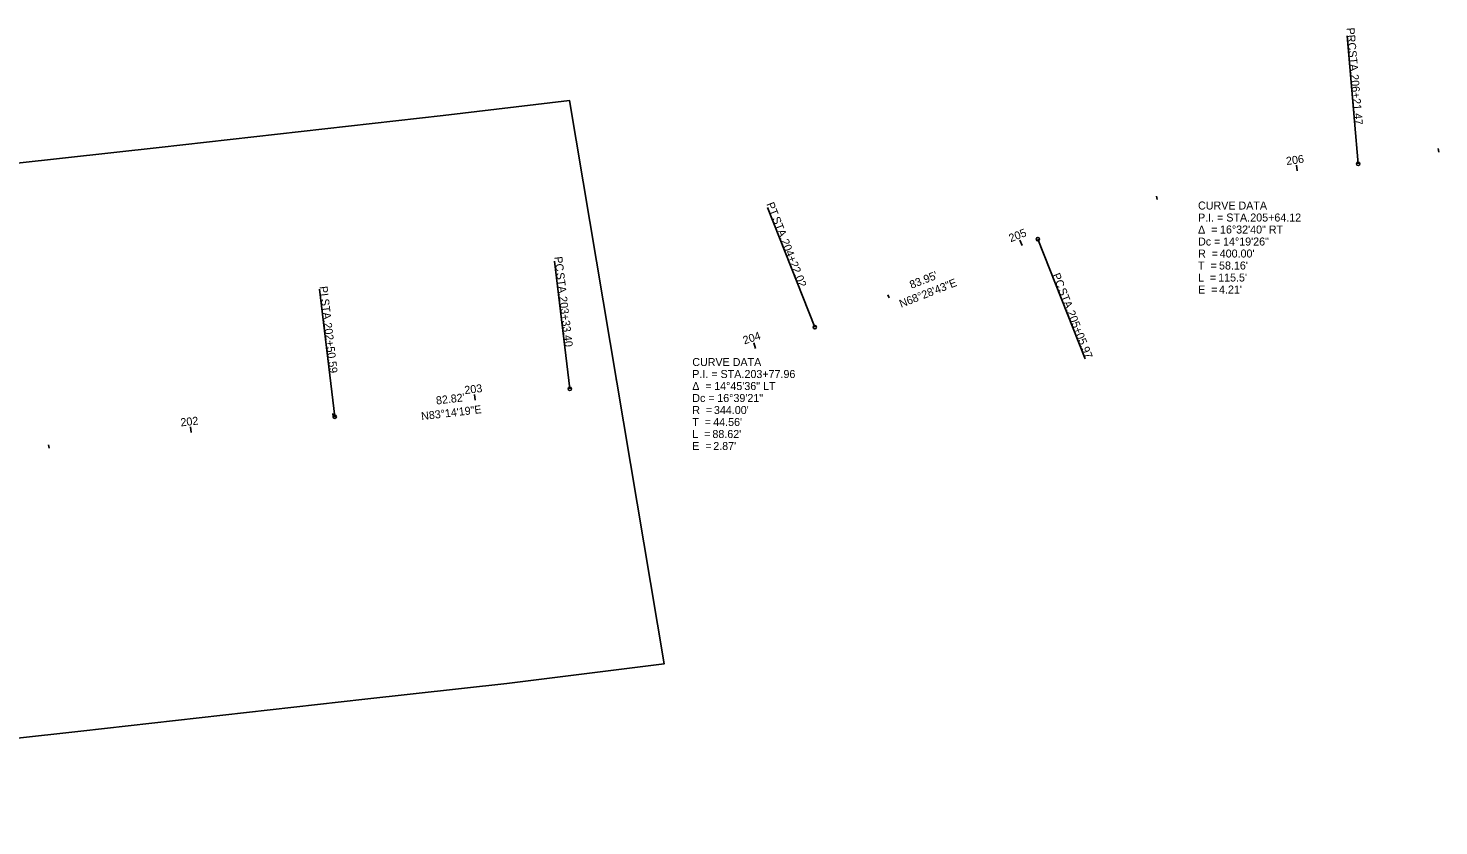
# Model space of a CAD drawing. Extents: x 1600023 to 1602105, y 286460 to 286887.
# Drawn here: x 1600548 to 1601041.6, y 286460.2 to 286739.4 of the extents above; entities that cross this region are included whole.
import ezdxf

# ---------------------------------------------------------------- set-up
doc = ezdxf.new("R2010")
doc.units = 0
for name, color, linetype in [('DT_X_Contour_Minor', 7, 'Continuous'), ('DT_X_Island', 7, 'Continuous'), ('DT_X_Terrain_Boundary', 7, 'Continuous'), ('DT_X_Void', 7, 'Continuous'), ('SC_Scratch3', 7, 'Continuous'), ('UT_X_Overhead_Electric', 7, 'Continuous')]:
    doc.layers.add(name, color=color, linetype=linetype)

msp = doc.modelspace()

# ---------------------------------------------------------------- linework, layer by layer
at = {"layer": 'DT_X_Island'}
for p, q in [((1601013.35, 286691.95), (1601009.45, 286736.78)), ((1600823.21, 286634.77), (1600806.71, 286676.63)), ((1600901.31, 286665.57), (1600917.82, 286623.7)), ((1600737.52, 286613.18), (1600732.22, 286657.87)), ((1600655.28, 286603.43), (1600649.98, 286648.12))]:
    msp.add_line(p, q, dxfattribs=at)
for centre in [(1601013.35, 286691.95), (1600901.31, 286665.57), (1600823.21, 286634.77), (1600737.52, 286613.18), (1600655.28, 286603.43)]:
    msp.add_circle(centre, 0.6, dxfattribs=at)
at = {"layer": 'SC_Scratch3'}
for p, q in [((1601041.56, 286696.1), (1601041.31, 286697.28)), ((1600992.02, 286689.51), (1600991.74, 286691.49)), ((1600943.08, 286679.43), (1600942.76, 286680.59)), ((1600895.76, 286663.38), (1600895.03, 286665.24)), ((1600849.25, 286645.03), (1600848.8, 286646.15)), ((1600802.49, 286627.35), (1600801.87, 286629.26)), ((1600753.95, 286615.53), (1600753.75, 286616.71)), ((1600704.35, 286609.25), (1600704.12, 286611.23)), ((1600654.7, 286603.36), (1600654.57, 286604.56)), ((1600605, 286597.91), (1600604.78, 286599.89)), ((1600555.3, 286592.45), (1600555.17, 286593.64))]:
    msp.add_line(p, q, dxfattribs=at)
at = {"layer": 'UT_X_Overhead_Electric'}
msp.add_lwpolyline([(1600246.12, 286659), (1600268.07, 286460.21), (1600317.77, 286465.7), (1600367.47, 286471.18), (1600417.32, 286476.69), (1600467.01, 286482.25), (1600516.7, 286487.82), (1600566.39, 286493.38), (1600616.08, 286498.95), (1600665.77, 286504.51), (1600715.46, 286510.08), (1600770.49, 286516.91), (1600737.4, 286714.15), (1600693.2, 286708.83), (1600643.51, 286703.27), (1600593.82, 286697.7), (1600544.13, 286692.14), (1600494.44, 286686.57), (1600444.75, 286681.01), (1600395.06, 286675.45), (1600345.52, 286669.97), (1600295.82, 286664.49)], close=True, dxfattribs=at)

# ---------------------------------------------------------------- texts
at = {"layer": 'DT_X_Contour_Minor'}
for s, rotation, p in [("83.95'", 21.5214, (1600857.07, 286648.17)), ("82.82'", 6.7614, (1600690.87, 286607.69))]:
    msp.add_text(s, height=2.8, rotation=rotation, dxfattribs=at).set_placement(p)
at = {"layer": 'DT_X_Island'}
for s, rotation, p in [('PRC', 274.977, (1601009.25, 286739.51)), (' STA. ', 274.977, (1601009.85, 286732.59)), ('206+21.47', 274.977, (1601010.67, 286723.18)), ('PT', 291.5214, (1600806.25, 286677.89)), (' STA. ', 291.5214, (1600807.87, 286673.79)), ('204+22.02', 291.5214, (1600811.34, 286664.99)), ('PC', 276.7614, (1600732.09, 286659.35)), (' STA. ', 276.7614, (1600732.63, 286654.8)), ('PC', 291.5214, (1600906.28, 286653.08)), ('PI', 276.7614, (1600649.92, 286648.98)), (' STA. ', 276.7614, (1600650.32, 286645.61)), ('203+33.40', 276.7614, (1600733.74, 286645.41)), (' STA. ', 291.5214, (1600907.96, 286648.81)), ('205+05.97', 291.5214, (1600911.43, 286640.02)), ('202+50.59', 276.7614, (1600651.43, 286636.23))]:
    msp.add_text(s, height=2.8, rotation=rotation, dxfattribs=at).set_placement(p)
at = {"layer": 'DT_X_Terrain_Boundary'}
for s, p in [('CURVE DATA', (1600957.33, 286675.96)), ('P.I. = STA. ', (1600957.33, 286671.76)), ('205+64.12', (1600975.6, 286671.76)), ('Δ  = ', (1600957.33, 286667.56)), ('16°32\'40" RT', (1600965.01, 286667.56)), ('Dc = ', (1600957.33, 286663.36)), ('14°19\'26"', (1600966.07, 286663.36)), ('R  = ', (1600957.33, 286659.16)), ("400.00'", (1600964.91, 286659.16)), ('T  = ', (1600957.33, 286654.96)), ("58.16'", (1600964.67, 286654.96)), ('L  = ', (1600957.33, 286650.76)), ('E  = ', (1600957.33, 286646.56)), ("115.5'", (1600964.37, 286650.76)), ("4.21'", (1600964.67, 286646.56)), ('CURVE DATA', (1600780.37, 286621.17)), ('P.I. = STA. ', (1600780.37, 286616.97)), ('203+77.96', (1600798.63, 286616.97)), ('Δ  = ', (1600780.37, 286612.77)), ('14°45\'36" LT', (1600788.04, 286612.77)), ('Dc = ', (1600780.37, 286608.57)), ('16°39\'21"', (1600789.11, 286608.57)), ('R  = ', (1600780.37, 286604.37)), ("344.00'", (1600787.95, 286604.37)), ('T  = ', (1600780.37, 286600.17)), ("44.56'", (1600787.7, 286600.17)), ('L  = ', (1600780.37, 286595.97)), ('E  = ', (1600780.37, 286591.77)), ("88.62'", (1600787.41, 286595.97)), ("2.87'", (1600787.71, 286591.77))]:
    msp.add_text(s, height=2.8, dxfattribs=at).set_placement(p)
at = {"layer": 'DT_X_Void'}
for s, rotation, p in [('N68°28\'43"E', 21.5214, (1600853.45, 286641.53)), ('N83°14\'19"E', 6.7614, (1600685.68, 286602.2))]:
    msp.add_text(s, height=2.8, rotation=rotation, dxfattribs=at).set_placement(p)
at = {"layer": 'SC_Scratch3'}
for s, rotation, p in [('206', 8.0525, (1600988.34, 286691.52)), ('205', 21.5214, (1600891.77, 286664.49)), ('204', 17.854, (1600798.61, 286628.73)), ('203', 6.7614, (1600700.81, 286611.34)), ('202', 6.2675, (1600601.46, 286600.03))]:
    msp.add_text(s, height=2.8, rotation=rotation, dxfattribs=at).set_placement(p)

doc.saveas('drawing.dxf')
